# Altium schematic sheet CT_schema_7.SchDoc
size 256 x 245 mm
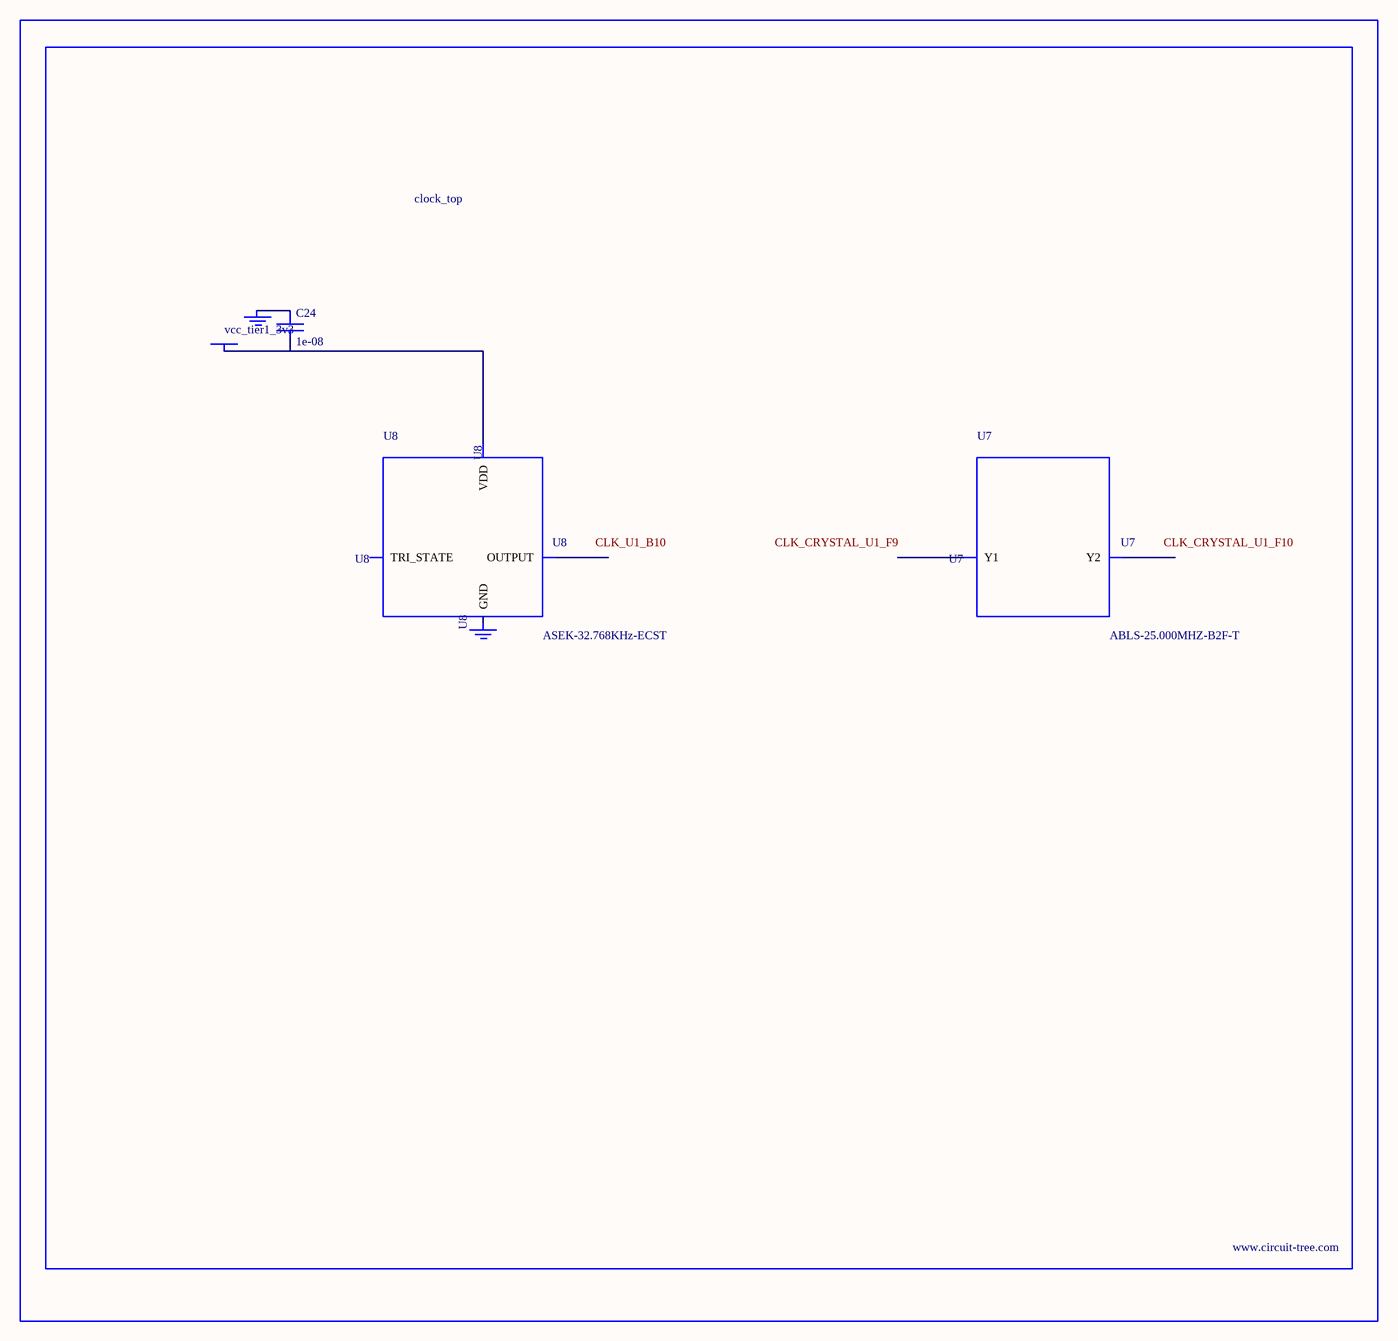
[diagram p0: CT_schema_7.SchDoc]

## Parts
BORDER6  (no value)
C24  1e-08  [C0402]
GND_INSTANCE_6_0  (no value)
GND_INSTANCE_6_1  (no value)
POWER_INSTANCE_6_0  vcc_tier1_3v3
U7  ABLS-25.000MHZ-B2F-T  [ABLS-25.000MHZ-B2F-T]
U8  ASEK-32.768KHz-ECST  [ASEK]

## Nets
NetC24_1: C24.1 GND_INSTANCE_6_0.0(GND)
NetC24_2: C24.2 POWER_INSTANCE_6_0.0(PWR) U8.4(VDD)

Not connected (* = marked no-connect by the designer): GND_INSTANCE_6_1 0(GND); U7 1(Y1) 2(Y2); U8 1(TRI_STATE) 2(GND) 3(OUTPUT)

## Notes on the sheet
- Labels drawn without touching a wire or pin: CLK_CRYSTAL_U1_F9, CLK_CRYSTAL_U1_F10, CLK_U1_B10

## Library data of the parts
BORDER6 = BORDER_PAGE6
C24 = C0402C103K3RAC
GND_INSTANCE_6_0 GND_INSTANCE_6_1 = GND
POWER_INSTANCE_6_0 = PWR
